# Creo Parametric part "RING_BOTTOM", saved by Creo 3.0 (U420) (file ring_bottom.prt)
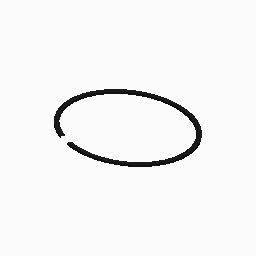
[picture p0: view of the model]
Units: millimeter Kilogram Sec (mmKs); MM, KILOGRAM, SECS

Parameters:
  MATERIAL = "GOE 32"

Created from: INLBS_PART_SOLID.PRT

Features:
  1. coordinate system "ORIGIN"
  2. datum plane "SIDE", "RIGHT"
  3. datum plane "DTM1", "TOP"
  4. datum plane "DTM2", "FRONT"
  5. datum axis "RING_AXIS"
  6. extrusion "Extrude 1"
  7. extruded cut "Extrude 2"

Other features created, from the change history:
  group "COPIED_GROUP"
